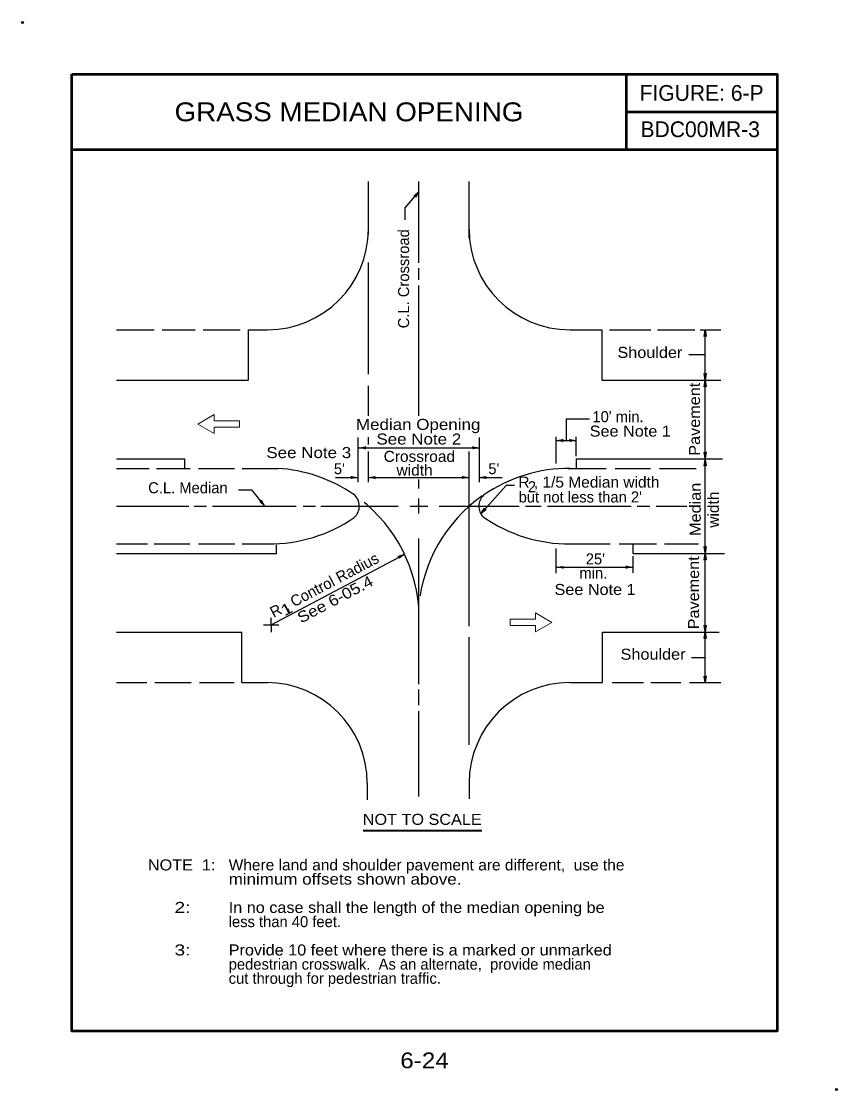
# Model space of a CAD drawing. Extents: x -2.269 to -1.594, y 3.09 to 3.974.
import ezdxf
from ezdxf.enums import TextEntityAlignment as Align

# ---------------------------------------------------------------- set-up
doc = ezdxf.new("R2010")
doc.units = 0
doc.header["$LTSCALE"] = 0.0036
doc.header["$PDMODE"] = 32
doc.header["$PDSIZE"] = 0.0018
doc.linetypes.add('LONG_DASHED', pattern=[7.5, 6, -1.5])
doc.layers.add('1', color=7, linetype='Continuous', lineweight=25)
doc.layers.add('60', color=7, linetype='Continuous', lineweight=13)

msp = doc.modelspace()

# ---------------------------------------------------------------- linework, layer by layer
at = {"layer": '1', "lineweight": 53}
for p, q in [((-1.768875, 3.930425), (-1.768875, 3.867925)), ((-1.768875, 3.899175), (-1.643875, 3.899175)), ((-2.227208, 3.867925), (-1.643875, 3.867925))]:
    msp.add_line(p, q, dxfattribs=at)
at = {"layer": '1'}
for p, q in [((-1.981992, 3.798292), (-1.981992, 3.841592)), ((-1.940325, 3.774392), (-1.940325, 3.841592)), ((-1.898658, 3.794575), (-1.898658, 3.841592)), ((-1.951642, 3.8197), (-1.940325, 3.833058)), ((-1.940275, 3.833133), (-1.943142, 3.82855)), ((-1.951642, 3.809975), (-1.951642, 3.8197)), ((-1.981992, 3.682183), (-1.981992, 3.774675)), ((-1.940325, 3.760267), (-1.940325, 3.769992)), ((-1.940325, 3.647625), (-1.940325, 3.755417)), ((-2.190325, 3.718875), (-2.1591, 3.718875)), ((-2.152475, 3.718875), (-2.125125, 3.718875)), ((-2.1185, 3.718875), (-2.08805, 3.718875)), ((-2.081433, 3.718875), (-2.065325, 3.718875)), ((-2.081433, 3.718875), (-2.081433, 3.677208)), ((-1.815325, 3.718875), (-1.78885, 3.718875)), ((-1.78885, 3.718875), (-1.78885, 3.677208)), ((-1.782675, 3.718875), (-1.748258, 3.718875)), ((-1.742958, 3.718875), (-1.712075, 3.718875)), ((-1.707658, 3.718875), (-1.690325, 3.718875)), ((-1.703408, 3.718767), (-1.702617, 3.713417)), ((-1.703408, 3.427208), (-1.703408, 3.718092)), ((-1.717017, 3.6986), (-1.70325, 3.6986)), ((-1.70345, 3.677433), (-1.704242, 3.682792)), ((-2.190325, 3.677208), (-2.081433, 3.677208)), ((-1.981992, 3.647625), (-1.981992, 3.672517)), ((-1.78885, 3.677208), (-1.690325, 3.677208)), ((-1.703417, 3.677133), (-1.702625, 3.671783)), ((-1.990558, 3.592892), (-1.990558, 3.629892)), ((-1.981992, 3.623933), (-1.981992, 3.630117)), ((-1.889975, 3.592892), (-1.889975, 3.629825)), ((-1.8266, 3.608242), (-1.8266, 3.630492)), ((-1.82645, 3.62725), (-1.810167, 3.62725)), ((-1.82635, 3.627392), (-1.821, 3.628183)), ((-1.810075, 3.62725), (-1.815425, 3.626458)), ((-1.810125, 3.614283), (-1.810125, 3.630492)), ((-1.990392, 3.621408), (-1.889958, 3.621408)), ((-1.98955, 3.62135), (-1.9842, 3.622142)), ((-1.981992, 3.592892), (-1.981992, 3.618117)), ((-1.898658, 3.473842), (-1.898658, 3.618117)), ((-1.89035, 3.621325), (-1.895708, 3.620533)), ((-1.70345, 3.612408), (-1.704242, 3.617758)), ((-2.190325, 3.6121), (-2.133917, 3.6121)), ((-2.133917, 3.604292), (-2.133917, 3.6121)), ((-1.810125, 3.6121), (-1.689208, 3.6121)), ((-1.810125, 3.6121), (-1.810125, 3.604292)), ((-1.703417, 3.611667), (-1.702625, 3.606308)), ((-2.190325, 3.604292), (-2.163342, 3.604292)), ((-2.1572, 3.604292), (-2.1293, 3.604292)), ((-2.122492, 3.604292), (-2.092625, 3.604292)), ((-2.086258, 3.604292), (-2.056667, 3.604292)), ((-1.8166, 3.604292), (-1.785417, 3.604292)), ((-1.77795, 3.604292), (-1.748508, 3.604292)), ((-1.74105, 3.604292), (-1.710742, 3.604292)), ((-2.009117, 3.596733), (-1.990558, 3.596733)), ((-1.99095, 3.596758), (-1.9963, 3.595967)), ((-1.981992, 3.596733), (-1.898658, 3.596733)), ((-1.981642, 3.596675), (-1.976292, 3.597467)), ((-1.940325, 3.587625), (-1.940325, 3.595067)), ((-1.8988, 3.59665), (-1.904158, 3.595858)), ((-1.889975, 3.596733), (-1.87125, 3.596733)), ((-1.889933, 3.5968), (-1.884583, 3.597592)), ((-2.0894, 3.586483), (-2.078625, 3.586483)), ((-2.078625, 3.586483), (-2.067867, 3.573117)), ((-2.190325, 3.573042), (-2.130417, 3.573042)), ((-2.126, 3.573042), (-2.11585, 3.573042)), ((-2.111, 3.573042), (-2.041717, 3.573042)), ((-2.0679, 3.573175), (-2.071883, 3.576833)), ((-2.035975, 3.573042), (-2.025833, 3.573042)), ((-2.021417, 3.573042), (-1.957425, 3.573042)), ((-1.947283, 3.573042), (-1.932717, 3.573042)), ((-1.940325, 3.566917), (-1.940325, 3.579283)), ((-1.92345, 3.573042), (-1.857258, 3.573042)), ((-1.851958, 3.573042), (-1.839167, 3.573042)), ((-1.833867, 3.573042), (-1.764583, 3.573042)), ((-1.759725, 3.573042), (-1.749133, 3.573042)), ((-1.743842, 3.573042), (-1.718642, 3.573042)), ((-1.8889, 3.566825), (-1.885925, 3.571342)), ((-1.940325, 3.4826), (-1.940325, 3.546392)), ((-2.190325, 3.541792), (-2.164667, 3.541792)), ((-2.159167, 3.541792), (-2.129742, 3.541792)), ((-2.122492, 3.541792), (-2.092408, 3.541792)), ((-2.086258, 3.541792), (-2.062992, 3.541792)), ((-1.8266, 3.517492), (-1.8266, 3.537925)), ((-1.816367, 3.541792), (-1.781892, 3.541792)), ((-1.774433, 3.541792), (-1.743683, 3.541792)), ((-1.763008, 3.533975), (-1.763008, 3.541792)), ((-1.737092, 3.541792), (-1.708975, 3.541792)), ((-1.703367, 3.5343), (-1.704158, 3.539658)), ((-2.062433, 3.47495), (-1.951875, 3.533383)), ((-1.952058, 3.533283), (-1.956417, 3.530075)), ((-1.763008, 3.533975), (-1.687458, 3.533975)), ((-1.763008, 3.517933), (-1.763008, 3.531767)), ((-1.703433, 3.533908), (-1.702642, 3.52855)), ((-1.82645, 3.52255), (-1.763008, 3.52255)), ((-1.826142, 3.522475), (-1.820792, 3.523267)), ((-1.763617, 3.52255), (-1.768967, 3.521758)), ((-2.062433, 3.47495), (-2.062433, 3.480658)), ((-1.940325, 3.425917), (-1.940325, 3.4826)), ((-2.190325, 3.468875), (-2.086725, 3.468875)), ((-2.086725, 3.427208), (-2.086725, 3.468875)), ((-2.0688, 3.47495), (-2.056058, 3.47495)), ((-2.062433, 3.47495), (-2.062433, 3.468792)), ((-1.788417, 3.427208), (-1.788417, 3.468875)), ((-1.788417, 3.468875), (-1.691842, 3.468875)), ((-1.703367, 3.469167), (-1.704158, 3.474517)), ((-1.703342, 3.468975), (-1.70255, 3.463625)), ((-1.898658, 3.375617), (-1.898658, 3.464617)), ((-1.714742, 3.447925), (-1.703533, 3.447925)), ((-1.703383, 3.427208), (-1.704175, 3.432558)), ((-2.190325, 3.427208), (-2.165283, 3.427208)), ((-2.158658, 3.427208), (-2.128658, 3.427208)), ((-2.121592, 3.427208), (-2.092908, 3.427208)), ((-2.086725, 3.427208), (-2.065325, 3.427208)), ((-1.815325, 3.427208), (-1.788417, 3.427208)), ((-1.780467, 3.427208), (-1.754433, 3.427208)), ((-1.748258, 3.427208), (-1.723542, 3.427208)), ((-1.716475, 3.427208), (-1.690325, 3.427208)), ((-1.940325, 3.408558), (-1.940325, 3.4213)), ((-1.940325, 3.332875), (-1.940325, 3.403508)), ((-1.982875, 3.343792), (-1.982875, 3.330083)), ((-1.898658, 3.343875), (-1.898658, 3.330933))]:
    msp.add_line(p, q, dxfattribs=at)
at = {"layer": '1', "lineweight": 35}
msp.add_line((-1.986325, 3.304792), (-1.888217, 3.304792), dxfattribs=at)
at = {"layer": '1', "lineweight": 53}
msp.add_lwpolyline([(-2.227208, 3.930425), (-1.643875, 3.930425), (-1.643875, 3.138758), (-2.227208, 3.138758)], close=True, dxfattribs=at)
at = {"layer": '1'}
for points in [[(-1.943142, 3.829742), (-1.944483, 3.829508), (-1.940225, 3.833175)], [(-1.943158, 3.82855), (-1.943133, 3.829733), (-1.943142, 3.829742)], [(-1.703392, 3.714325), (-1.704258, 3.713283), (-1.703392, 3.718833)], [(-1.702633, 3.713408), (-1.703375, 3.714325), (-1.703392, 3.714325)], [(-1.704217, 3.6828), (-1.703475, 3.681883), (-1.703458, 3.681883)], [(-1.703458, 3.681883), (-1.702592, 3.682925), (-1.703458, 3.677375)], [(-1.703408, 3.672683), (-1.704267, 3.671642), (-1.703408, 3.6772)], [(-1.702642, 3.671767), (-1.703383, 3.672683), (-1.703408, 3.672683)], [(-1.818217, 3.62725), (-1.818217, 3.645183), (-1.799167, 3.645183)], [(-1.821908, 3.627408), (-1.820867, 3.626542), (-1.826417, 3.627408)], [(-1.820992, 3.628167), (-1.821908, 3.627425), (-1.821908, 3.627408)], [(-1.814517, 3.627242), (-1.815558, 3.6281), (-1.810008, 3.627242)], [(-1.815433, 3.626475), (-1.814517, 3.627217), (-1.814517, 3.627242)], [(-1.9851, 3.621367), (-1.984058, 3.6205), (-1.989617, 3.621367)], [(-1.984183, 3.622125), (-1.9851, 3.621383), (-1.9851, 3.621367)], [(-1.8948, 3.621308), (-1.895842, 3.622175), (-1.890292, 3.621308)], [(-1.895717, 3.62055), (-1.8948, 3.621292), (-1.8948, 3.621308)], [(-1.704217, 3.617767), (-1.703475, 3.61685), (-1.703458, 3.61685)], [(-1.703458, 3.61685), (-1.702592, 3.617892), (-1.703458, 3.612342)], [(-1.703408, 3.607217), (-1.704267, 3.606175), (-1.703408, 3.611725)], [(-1.702642, 3.6063), (-1.703383, 3.607217), (-1.703408, 3.607217)], [(-1.995392, 3.59675), (-1.996433, 3.597608), (-1.990883, 3.59675)], [(-1.996308, 3.595983), (-1.995392, 3.596725), (-1.995392, 3.59675)], [(-1.9772, 3.596683), (-1.976158, 3.595817), (-1.981708, 3.596683)], [(-1.976283, 3.597442), (-1.9772, 3.596708), (-1.9772, 3.596683)], [(-1.90325, 3.596642), (-1.904292, 3.597508), (-1.898742, 3.596642)], [(-1.904167, 3.595883), (-1.90325, 3.596625), (-1.90325, 3.596642)], [(-1.885492, 3.596808), (-1.88445, 3.595942), (-1.89, 3.596808)], [(-1.884575, 3.597567), (-1.885492, 3.596833), (-1.885492, 3.596808)], [(-1.8611, 3.590125), (-1.868117, 3.590125), (-1.88895, 3.566783)], [(-2.071867, 3.576858), (-2.070725, 3.576608), (-2.070708, 3.576633)], [(-2.070708, 3.576633), (-2.070692, 3.577975), (-2.067867, 3.573117)], [(-1.885942, 3.570142), (-1.8846, 3.570342), (-1.88895, 3.566783)], [(-1.8859, 3.571333), (-1.885967, 3.570158), (-1.885942, 3.570142)], [(-2.190325, 3.533975), (-2.057925, 3.533975), (-2.057925, 3.541183)], [(-1.704133, 3.539667), (-1.703392, 3.53875), (-1.703375, 3.53875)], [(-1.703375, 3.53875), (-1.702508, 3.539792), (-1.703375, 3.534242)], [(-1.955992, 3.531183), (-1.957308, 3.531458), (-1.952008, 3.5333)], [(-1.956433, 3.530083), (-1.955975, 3.531167), (-1.955992, 3.531183)], [(-1.703425, 3.529458), (-1.704292, 3.528417), (-1.703425, 3.533967)], [(-1.702667, 3.528542), (-1.703408, 3.529458), (-1.703425, 3.529458)], [(-1.8217, 3.522492), (-1.820658, 3.521625), (-1.826208, 3.522492)], [(-1.820783, 3.52325), (-1.8217, 3.522508), (-1.8217, 3.522492)], [(-1.768058, 3.522542), (-1.7691, 3.523408), (-1.76355, 3.522542)], [(-1.768975, 3.521783), (-1.768058, 3.522517), (-1.768058, 3.522542)], [(-1.703333, 3.464533), (-1.7042, 3.463492), (-1.703333, 3.469042)], [(-1.704133, 3.474533), (-1.703392, 3.473617), (-1.703375, 3.473617)], [(-1.703375, 3.473617), (-1.702508, 3.474658), (-1.703375, 3.4691)], [(-1.702575, 3.463617), (-1.703308, 3.464533), (-1.703333, 3.464533)], [(-1.704158, 3.432575), (-1.703417, 3.431658), (-1.703392, 3.431658)], [(-1.703392, 3.431658), (-1.702533, 3.4327), (-1.703392, 3.427142)]]:
    msp.add_lwpolyline(points, dxfattribs=at)
for centre, radius, start, end in [((-2.065321, 3.802206), 0.083333, 270, 0), ((-1.815321, 3.802206), 0.083333, 180, 270), ((-2.064739, 3.479383), 0.125168, 55.85029, 86.44603), ((-1.815799, 3.47969), 0.124602, 89.63154, 124.68361), ((-2.001967, 3.572998), 0.0125, 310.71505, 52.57257), ((-1.878092, 3.572977), 0.0125, 133.46075, 224.57694), ((-1.815676, 3.666716), 0.124928, 235.18199, 270.31599), ((-2.063979, 3.665961), 0.124176, 269.54435, 304.41522), ((-1.878092, 3.572977), 0.0125, 237.40479, 238.18502), ((-2.066206, 3.34379), 0.083333, 0, 90), ((-1.815321, 3.343873), 0.083333, 90, 180)]:
    msp.add_arc(centre, radius, start, end, dxfattribs=at)
at = {"layer": '1', "linetype": 'LONG_DASHED'}
for centre, major_axis, ratio, start_param, end_param in [((-2.064739, 3.479383), (-0.000248, 0.125167), 0.997623, 4.7929779, 5.6835102), ((-1.815799, 3.47969), (-0.124931, 0.000803), 0.997344, 5.3325571, 6.2091451)]:
    msp.add_ellipse(centre, major_axis=major_axis, ratio=ratio, start_param=start_param, end_param=end_param, dxfattribs=at)
at = {"layer": '1'}
for p in [(-2.268092, 3.973067), (-1.594758, 3.090567)]:
    msp.add_point(p, dxfattribs=at)
at = {"layer": '60'}
for points in [[(-2.088625, 3.638375), (-2.109583, 3.638375), (-2.109583, 3.633167), (-2.123117, 3.640975), (-2.109583, 3.648792), (-2.109583, 3.643583), (-2.088625, 3.643583)], [(-1.864608, 3.474325), (-1.84365, 3.474325), (-1.84365, 3.469117), (-1.830117, 3.476925), (-1.84365, 3.484742), (-1.84365, 3.479533), (-1.864608, 3.479533)]]:
    msp.add_lwpolyline(points, close=True, dxfattribs=at)

# ---------------------------------------------------------------- texts
at = {"layer": '1'}
for s, height, p in [('FIGURE: 6-P', 0.01303, (-1.706379, 3.908283)), ('BDC00MR-3', 0.01303, (-1.707521, 3.87825)), ("25'", 0.009117, (-1.794221, 3.524875)), ('min. ', 0.009117, (-1.794212, 3.51315))]:
    msp.add_text(s, height=height, dxfattribs=at).set_placement(p, align=Align.CENTER)
for s, height, width, p in [('GRASS MEDIAN OPENING', 0.01562, 1.1, (-1.998042, 3.891358)), ('NOT TO SCALE', 0.009117, 1.1, (-1.937446, 3.309442)), ('6-24', 0.01303, 1.15, (-1.935546, 3.10815))]:
    msp.add_text(s, height=height, dxfattribs=dict(at, width=width)).set_placement(p, align=Align.CENTER)
for s, rotation, p in [('C.L. Crossroad', 90, (-1.9483, 3.720117)), ('R , Control Radius', 27.859, (-2.0603, 3.480475))]:
    msp.add_text(s, height=0.009117, rotation=rotation, dxfattribs=at).set_placement(p)
for s, width, p in [('Shoulder', 1.1, (-1.775967, 3.695667)), ('Median Opening', 1.15, (-1.992242, 3.636083)), ('See Note 1', 1.1, (-1.7989, 3.630558)), ('See Note 2', 1.15, (-1.975342, 3.623992)), ('See Note 3', 1.15, (-2.066358, 3.612792)), ('Crossroad', 1.05, (-1.969358, 3.609633)), ('width', 1.05, (-1.9587, 3.5983)), ('R , 1/5 Median width', 1.05, (-1.8579, 3.588383)), ('See Note 1', 1.1, (-1.828033, 3.499583)), ('Shoulder', 1.1, (-1.77335, 3.446042)), ('NOTE  1:', 1.1, (-2.164367, 3.271775)), ('Where land and shoulder pavement are different,  use the', 1.05, (-2.0975, 3.271783)), ('minimum offsets shown above.', 1.15, (-2.0975, 3.260058)), ('     2:', 1.3, (-2.164367, 3.2366)), ('In no case shall the length of the median opening be', 1.1, (-2.0975, 3.236608)), ('     3:', 1.3, (-2.164367, 3.201425)), ('Provide 10 feet where there is a marked or unmarked', 1.1, (-2.0975, 3.201433))]:
    msp.add_text(s, height=0.009117, dxfattribs=dict(at, width=width)).set_placement(p)
for s, rotation, width, p in [('Pavement', 90, 1.1, (-1.707667, 3.61475)), ('Median', 90, 1.1, (-1.70705, 3.548417)), ('width', 90, 1.05, (-1.692108, 3.555208)), ('Pavement', 90, 1.1, (-1.70845, 3.4712)), ('See 6-05.4', 27.859, 1.15, (-2.037667, 3.475925)), ('1', 27.859, 1.3, (-2.051417, 3.481842))]:
    msp.add_text(s, height=0.009117, rotation=rotation, dxfattribs=dict(at, width=width)).set_placement(p)
for s, p in [("10' min.", (-1.796675, 3.6425)), ("5'", (-2.010517, 3.599475)), ("5'", (-1.882792, 3.599475)), ('C.L. Median', (-2.164108, 3.5837)), ('2', (-1.850067, 3.584542)), ("but not less than 2'", (-1.857692, 3.576075)), ('less than 40 feet.', (-2.0975, 3.224883)), ('pedestrian crosswalk.  As an alternate,  provide median', (-2.0975, 3.189708)), ('cut through for pedestrian traffic.', (-2.0975, 3.177983))]:
    msp.add_text(s, height=0.009117, dxfattribs=at).set_placement(p)

doc.saveas('drawing.dxf')
